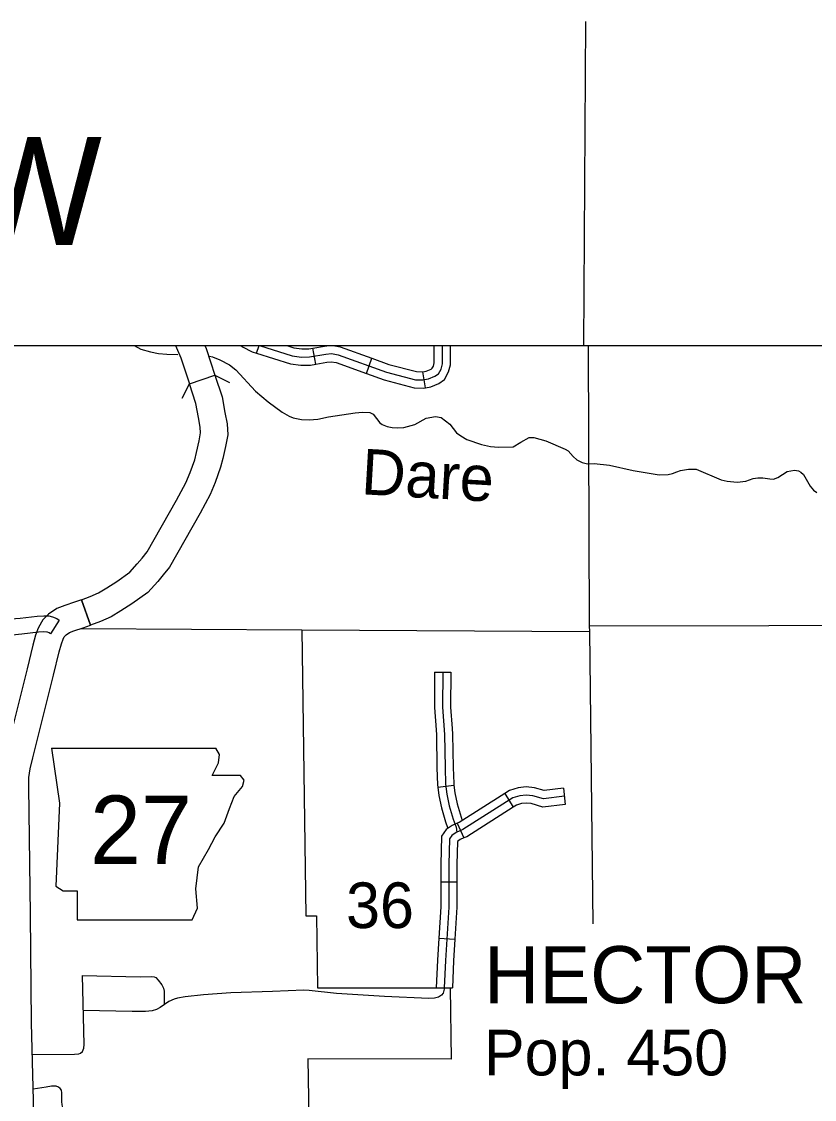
# Model space of a CAD drawing. Extents: x 1373862 to 1376999, y 1168398 to 1170455.
# Drawn here: x 1374821 to 1374967.8, y 1169439.9 to 1169639.4 of the extents above; entities that cross this region are included whole.
import ezdxf

# ---------------------------------------------------------------- set-up
doc = ezdxf.new("R2010")
doc.units = 0
for name, color, linetype in [('Level 10', 7, 'Continuous'), ('Level 21', 7, 'Continuous'), ('Level 24', 7, 'Continuous'), ('Level 31', 7, 'Continuous'), ('Level 32', 7, 'Continuous'), ('Level 33', 7, 'Continuous'), ('Level 34', 7, 'Continuous'), ('Level 35', 7, 'Continuous'), ('Level 37', 7, 'Continuous'), ('Level 4', 7, 'Continuous'), ('Level 45', 7, 'Continuous'), ('Level 5', 7, 'Continuous'), ('Level 6', 7, 'Continuous'), ('R_Dimension', 7, 'Continuous'), ('R_Draft', 7, 'Continuous')]:
    doc.layers.add(name, color=color, linetype=linetype)

msp = doc.modelspace()

# ---------------------------------------------------------------- linework, layer by layer
at = {"layer": 'Level 10'}
for p, q in [((1374852.08, 1169572.38), (1374856.82, 1169573.97)), ((1374833.79, 1169527.69), (1374832.11, 1169532.4)), ((1374832.11, 1169532.4), (1374833.79, 1169527.69)), ((1374833.79, 1169527.69), (1374832.11, 1169532.4))]:
    msp.add_line(p, q, dxfattribs=at)
for points in [[(1374849.53, 1169579.43), (1374849.72, 1169579.03), (1374850.48, 1169577.15), (1374852.08, 1169572.38)], [(1374854.95, 1169579.43), (1374855.17, 1169578.88), (1374856.82, 1169573.97)], [(1374856.82, 1169573.97), (1374858.16, 1169569.98), (1374858.66, 1169567.06), (1374859.07, 1169564.98), (1374859.18, 1169562.94), (1374858.78, 1169560.78), (1374858.25, 1169558.52), (1374857.87, 1169556.91), (1374856.87, 1169554.11), (1374855.93, 1169551.89), (1374854.07, 1169548.42), (1374848.39, 1169538.45), (1374847.22, 1169536.98), (1374846.23, 1169535.76), (1374844.38, 1169533.73), (1374841.44, 1169531.61), (1374839.41, 1169530.35), (1374837.58, 1169529.26), (1374835.63, 1169528.35), (1374833.79, 1169527.69)], [(1374832.11, 1169532.4), (1374833.73, 1169532.98), (1374835.24, 1169533.68), (1374836.81, 1169534.62), (1374838.66, 1169535.77), (1374841.04, 1169537.48), (1374842.44, 1169539.02), (1374843.32, 1169540.11), (1374844.24, 1169541.26), (1374849.69, 1169550.84), (1374851.41, 1169554.05), (1374852.21, 1169555.93), (1374853.07, 1169558.32), (1374853.38, 1169559.65), (1374853.88, 1169561.8), (1374854.15, 1169563.27), (1374854.1, 1169564.37), (1374853.75, 1169566.16), (1374853.3, 1169568.75), (1374852.08, 1169572.38)], [(1374832.11, 1169532.4), (1374830.81, 1169531.92), (1374829.04, 1169531.36), (1374827.55, 1169530.79), (1374826.02, 1169529.74), (1374824.96, 1169528.66), (1374824.68, 1169528.26), (1374824.12, 1169527.12), (1374823.62, 1169525.83), (1374823.12, 1169524.01), (1374822.08, 1169519.63), (1374818.21, 1169504.28), (1374817.73, 1169502.04), (1374817.38, 1169499.94), (1374817.35, 1169497.74), (1374817.69, 1169474.07), (1374817.87, 1169454.03), (1374818.37, 1169434.73), (1374818.71, 1169423.46)], [(1374823.71, 1169423.61), (1374823.36, 1169434.87), (1374822.87, 1169454.11), (1374822.69, 1169474.13), (1374822.35, 1169497.74), (1374822.37, 1169499.49), (1374822.64, 1169501.1), (1374823.08, 1169503.14), (1374826.94, 1169518.45), (1374827.96, 1169522.77), (1374828.38, 1169524.26), (1374828.7, 1169525.12), (1374828.92, 1169525.55), (1374829.25, 1169525.9), (1374829.88, 1169526.33), (1374830.68, 1169526.63), (1374832.43, 1169527.19), (1374833.79, 1169527.69)]]:
    msp.add_lwpolyline(points, dxfattribs=at)
at = {"layer": 'Level 21'}
for p, q in [((1374826.54, 1169504.92), (1374828.07, 1169494.77)), ((1374857.67, 1169503.74), (1374856.97, 1169504.91)), ((1374857.5, 1169502.22), (1374857.67, 1169503.74)), ((1374856.32, 1169499.85), (1374857.5, 1169502.22)), ((1374861.56, 1169499.85), (1374856.32, 1169499.85)), ((1374862.24, 1169499), (1374861.56, 1169499.85)), ((1374860.38, 1169495.96), (1374861.9, 1169497.82)), ((1374861.9, 1169497.82), (1374862.24, 1169499)), ((1374859.53, 1169493.76), (1374860.38, 1169495.96)), ((1374828.07, 1169494.77), (1374827.39, 1169479.38)), ((1374858.52, 1169491.05), (1374859.53, 1169493.76)), ((1374856.83, 1169488.51), (1374858.52, 1169491.05)), ((1374855.64, 1169486.14), (1374856.83, 1169488.51)), ((1374853.78, 1169482.93), (1374855.64, 1169486.14)), ((1374853.27, 1169478.87), (1374853.78, 1169482.93)), ((1374827.39, 1169479.38), (1374828.74, 1169478.53)), ((1374828.74, 1169478.53), (1374831.28, 1169478.53)), ((1374831.28, 1169478.53), (1374831.28, 1169473.12)), ((1374853.61, 1169475.32), (1374853.27, 1169478.87)), ((1374852.6, 1169473.12), (1374853.61, 1169475.32)), ((1374831.28, 1169473.12), (1374852.6, 1169473.12))]:
    msp.add_line(p, q, dxfattribs=at)
msp.add_lwpolyline([(1374826.54, 1169504.92), (1374856.97, 1169504.91)], dxfattribs=at)
at = {"layer": 'Level 31'}
msp.add_line((1374828, 1169528.61), (1374826.36, 1169526.1), dxfattribs=at)
for points in [[(1374816.7, 1169528.68), (1374816.81, 1169528.68), (1374819.03, 1169528.84), (1374820.74, 1169528.99), (1374823.89, 1169529.37), (1374825.13, 1169529.44), (1374826.05, 1169529.4), (1374826.74, 1169529.25), (1374827.53, 1169528.92), (1374828, 1169528.61)], [(1374826.36, 1169526.1), (1374826.12, 1169526.26), (1374825.85, 1169526.37), (1374825.67, 1169526.41), (1374825.15, 1169526.43), (1374824.15, 1169526.38), (1374821.05, 1169526), (1374819.27, 1169525.85), (1374816.99, 1169525.69), (1374816.86, 1169525.68)]]:
    msp.add_lwpolyline(points, dxfattribs=at)
at = {"layer": 'Level 32'}
for p, q in [((1374864.53, 1169578.02), (1374864.97, 1169579.43)), ((1374875.48, 1169576.02), (1374874.96, 1169578.98)), ((1374884.86, 1169574.28), (1374885.87, 1169577.1)), ((1374895.78, 1169571.65), (1374895.3, 1169574.61)), ((1374921.3, 1169497.5), (1374921.66, 1169494.52)), ((1374910.44, 1169496.52), (1374912.04, 1169493.98)), ((1374901.67, 1169491.04), (1374902.89, 1169488.3)), ((1374898.61, 1169480.21), (1374901.61, 1169480.21)), ((1374898.25, 1169469.75), (1374901.24, 1169469.57))]:
    msp.add_line(p, q, dxfattribs=at)
for points in [[(1374861.58, 1169579.43), (1374861.89, 1169579.19), (1374863.68, 1169578.28), (1374864.53, 1169578.02)], [(1374865.05, 1169579.43), (1374871.09, 1169577.54), (1374872.82, 1169577.33), (1374874.34, 1169577.35), (1374877.31, 1169577.87), (1374878.38, 1169577.95), (1374879.6, 1169577.76), (1374888.56, 1169574.54), (1374893.92, 1169573.13), (1374895.3, 1169573.09), (1374896.32, 1169573.26), (1374897.53, 1169573.78), (1374898.17, 1169574.19), (1374898.66, 1169575.11), (1374898.91, 1169576.07), (1374898.91, 1169579.43)], [(1374870.09, 1169579.43), (1374871.41, 1169579.02), (1374872.9, 1169578.83), (1374874.2, 1169578.84), (1374874.96, 1169578.98)], [(1374874.96, 1169578.98), (1374877.12, 1169579.36), (1374877.97, 1169579.43)], [(1374878.67, 1169579.43), (1374879.98, 1169579.22), (1374885.87, 1169577.1)], [(1374895.3, 1169574.61), (1374895.89, 1169574.71), (1374896.83, 1169575.11), (1374897.03, 1169575.25), (1374897.26, 1169575.66), (1374897.41, 1169576.26), (1374897.41, 1169579.43)], [(1374895.78, 1169571.65), (1374896.74, 1169571.81), (1374898.24, 1169572.45), (1374899.31, 1169573.14), (1374900.07, 1169574.56), (1374900.41, 1169575.87), (1374900.41, 1169579.43)], [(1374864.53, 1169578.02), (1374870.77, 1169576.07), (1374872.73, 1169575.83), (1374874.48, 1169575.85), (1374875.48, 1169576.02)], [(1374885.87, 1169577.1), (1374889.01, 1169575.97), (1374894.13, 1169574.62), (1374895.2, 1169574.6), (1374895.3, 1169574.61)], [(1374875.48, 1169576.02), (1374877.5, 1169576.38), (1374878.32, 1169576.44), (1374879.23, 1169576.3), (1374884.86, 1169574.28)], [(1374884.86, 1169574.28), (1374888.12, 1169573.1), (1374893.71, 1169571.63), (1374895.4, 1169571.59), (1374895.78, 1169571.65)], [(1374921.3, 1169497.5), (1374917.76, 1169497.07), (1374915.93, 1169497.61), (1374914.42, 1169497.75), (1374912.95, 1169497.6), (1374911.33, 1169497.09), (1374910.44, 1169496.52)], [(1374921.48, 1169496.01), (1374917.63, 1169495.54), (1374915.65, 1169496.13), (1374914.42, 1169496.24), (1374913.26, 1169496.13), (1374911.97, 1169495.72), (1374902.72, 1169489.86), (1374901.46, 1169489.3), (1374900.66, 1169488.75), (1374900.22, 1169488.15), (1374900.11, 1169483.39), (1374900.1, 1169475.52), (1374899.49, 1169465.63), (1374899.25, 1169460.57)], [(1374910.44, 1169496.52), (1374902.01, 1169491.19), (1374901.67, 1169491.04)], [(1374912.04, 1169493.98), (1374903.42, 1169488.53), (1374902.89, 1169488.3)], [(1374921.66, 1169494.52), (1374917.5, 1169494.02), (1374915.36, 1169494.65), (1374914.43, 1169494.73), (1374913.56, 1169494.65), (1374912.61, 1169494.35), (1374912.04, 1169493.98)], [(1374901.67, 1169491.04), (1374900.73, 1169490.62), (1374899.6, 1169489.84), (1374898.73, 1169488.66), (1374898.61, 1169483.41), (1374898.61, 1169480.21)], [(1374902.89, 1169488.3), (1374902.2, 1169487.99), (1374901.72, 1169487.66), (1374901.71, 1169487.65), (1374901.61, 1169483.37), (1374901.61, 1169480.21)], [(1374898.61, 1169480.21), (1374898.6, 1169475.57), (1374898.25, 1169469.75)], [(1374901.61, 1169480.21), (1374901.6, 1169475.47), (1374901.24, 1169469.57)], [(1374898.25, 1169469.75), (1374898, 1169465.71), (1374897.75, 1169460.57), (1374900.75, 1169460.57)], [(1374901.24, 1169469.57), (1374900.99, 1169465.54), (1374900.75, 1169460.57)]]:
    msp.add_lwpolyline(points, dxfattribs=at)
at = {"layer": 'Level 33'}
for points in [[(1374823.02, 1169448.19), (1374830.82, 1169448.25), (1374831.59, 1169448.31), (1374831.91, 1169448.44), (1374832.27, 1169448.8), (1374832.54, 1169449.37), (1374832.59, 1169450.05), (1374832.29, 1169462.84)], [(1374874.24, 1169460.09), (1374873.26, 1169460.12), (1374867.49, 1169459.9), (1374859.74, 1169459.63), (1374854.68, 1169459.27), (1374851.31, 1169458.92), (1374849.86, 1169458.65), (1374849.24, 1169458.45), (1374848.29, 1169458.02), (1374846.65, 1169456.9), (1374845.97, 1169456.52), (1374845.18, 1169456.28), (1374843.93, 1169456.17), (1374841.51, 1169456.17), (1374832.44, 1169456.39)], [(1374834.79, 1169433.95), (1374834.54, 1169437.35), (1374834.43, 1169437.73), (1374834.25, 1169437.95), (1374834.02, 1169438.04), (1374833.69, 1169438.09), (1374833.4, 1169438.06), (1374830.73, 1169437.54), (1374830.2, 1169437.5), (1374829.68, 1169437.56), (1374829.28, 1169437.68), (1374828.9, 1169438.01), (1374828.67, 1169438.43), (1374828.53, 1169438.89), (1374828.47, 1169439.54), (1374828.5, 1169441.1), (1374828.42, 1169441.6), (1374828.18, 1169441.93), (1374827.86, 1169442.2), (1374827.4, 1169442.35), (1374827.03, 1169442.38), (1374826.55, 1169442.37), (1374825.56, 1169442.2), (1374823.19, 1169441.77)]]:
    msp.add_lwpolyline(points, dxfattribs=at)
at = {"layer": 'Level 34'}
for points in [[(1374832.29, 1169462.84), (1374842.96, 1169462.62), (1374845.1, 1169462.67), (1374845.54, 1169462.62), (1374845.84, 1169462.46), (1374846.33, 1169461.97), (1374846.98, 1169461.1), (1374847.28, 1169460.47), (1374847.42, 1169459.95), (1374847.44, 1169457.44)], [(1374899.25, 1169460.57), (1374899.24, 1169460.3), (1374899.04, 1169459.55), (1374898.76, 1169459.23), (1374898.72, 1169459.2), (1374898.21, 1169458.85), (1374897.44, 1169458.65), (1374896.4, 1169458.58), (1374888.21, 1169458.94), (1374879.33, 1169459.53), (1374874.24, 1169460.09)]]:
    msp.add_lwpolyline(points, dxfattribs=at)
at = {"layer": 'Level 35'}
for points in [[(1374841.83, 1169579.43), (1374843.08, 1169578.81), (1374844.87, 1169578.27), (1374846.34, 1169577.95), (1374847.92, 1169577.83), (1374849.94, 1169577.81)], [(1374855.81, 1169577.46), (1374856.38, 1169577.36), (1374857.73, 1169576.83), (1374859.51, 1169575.9), (1374860.68, 1169574.97), (1374864.32, 1169571.01), (1374866.69, 1169569.05), (1374869.26, 1169567.15), (1374870.52, 1169566.4), (1374871.31, 1169566.1), (1374872.86, 1169565.74), (1374874.24, 1169565.68), (1374875.88, 1169565.82), (1374877.85, 1169566.28), (1374882.75, 1169566.97), (1374884.15, 1169567.09), (1374885.51, 1169567.04), (1374886.1, 1169566.72), (1374887.32, 1169565.17), (1374887.79, 1169564.84), (1374888.7, 1169564.48), (1374889.6, 1169564.27), (1374890.6, 1169564.19), (1374891.76, 1169564.28), (1374893.81, 1169564.86), (1374895.9, 1169565.98), (1374897.63, 1169566.29), (1374898.67, 1169566.13), (1374899.49, 1169565.53), (1374900.31, 1169564.87), (1374901.53, 1169563.32), (1374902.3, 1169562.74), (1374903.42, 1169562.09), (1374906.17, 1169561.14), (1374907.84, 1169560.76), (1374909.32, 1169560.62), (1374912.04, 1169560.69), (1374913.45, 1169561.59), (1374914.99, 1169562.4), (1374915.83, 1169562.44), (1374918.07, 1169561.84), (1374921.63, 1169560.27), (1374922.2, 1169559.96), (1374923.1, 1169558.94), (1374923.82, 1169558.32), (1374924.75, 1169557.78), (1374925.76, 1169557.57), (1374927, 1169557.64), (1374929.83, 1169557.28), (1374934.21, 1169556.35), (1374939.01, 1169555.54), (1374940.71, 1169555.6), (1374941.47, 1169555.76), (1374942.28, 1169556.07)], [(1374942.28, 1169556.07), (1374943, 1169556.31), (1374944.45, 1169556.59), (1374945.91, 1169556.56), (1374950.52, 1169554.62), (1374951.61, 1169554.33), (1374953.47, 1169554.18), (1374955.05, 1169554.32), (1374956.46, 1169554.82), (1374957.27, 1169554.96), (1374958.19, 1169554.99), (1374959.5, 1169554.76), (1374960.18, 1169554.74), (1374961.01, 1169555.04), (1374962.7, 1169556.15), (1374964.1, 1169556.37), (1374964.8, 1169556.25), (1374965.23, 1169556.02), (1374965.72, 1169555.57), (1374967.01, 1169553.42), (1374967.61, 1169552.71), (1374968.22, 1169552.23)]]:
    msp.add_lwpolyline(points, dxfattribs=at)
at = {"layer": 'Level 37'}
for points in [[(1374856.82, 1169573.97), (1374859.51, 1169572.64)], [(1374850.75, 1169569.69), (1374852.08, 1169572.38)]]:
    msp.add_lwpolyline(points, dxfattribs=at)
at = {"layer": 'Level 4'}
msp.add_lwpolyline([(1374925.92, 1169579.43), (1374926.1, 1169527.55), (1374926.11, 1169526.53), (1374926.76, 1169472.39)], dxfattribs=at)
at = {"layer": 'Level 45'}
for p, q in [((1374897.48, 1169519), (1374900.48, 1169518.98)), ((1374898.06, 1169497.72), (1374901.04, 1169498.06))]:
    msp.add_line(p, q, dxfattribs=at)
for points in [[(1374897.48, 1169519), (1374897.43, 1169512.44), (1374897.73, 1169508.33)], [(1374898.98, 1169518.99), (1374898.93, 1169512.49), (1374899.3, 1169507.46), (1374899.4, 1169501.33), (1374899.51, 1169498.26), (1374899.72, 1169496.41), (1374900.19, 1169494.24), (1374900.93, 1169491.76), (1374901.46, 1169490.27), (1374901.61, 1169489.37)], [(1374900.48, 1169518.98), (1374900.43, 1169512.53), (1374900.72, 1169508.55)], [(1374897.73, 1169508.33), (1374897.8, 1169507.39), (1374897.9, 1169501.29), (1374898.01, 1169498.15), (1374898.06, 1169497.72)], [(1374900.72, 1169508.55), (1374900.79, 1169507.53), (1374900.9, 1169501.37), (1374901, 1169498.37), (1374901.04, 1169498.06)], [(1374898.06, 1169497.72), (1374898.24, 1169496.16), (1374898.74, 1169493.87), (1374899.51, 1169491.29), (1374899.88, 1169490.23)], [(1374901.04, 1169498.06), (1374901.2, 1169496.66), (1374901.65, 1169494.62), (1374902.56, 1169491.54)]]:
    msp.add_lwpolyline(points, dxfattribs=at)
at = {"layer": 'Level 5'}
for points in [[(1374926.1, 1169527.55), (1375025.83, 1169527.76)], [(1374872.9, 1169526.83), (1374926.11, 1169526.53)]]:
    msp.add_lwpolyline(points, dxfattribs=at)
at = {"layer": 'Level 6'}
for points in [[(1374832.06, 1169527.07), (1374872.9, 1169526.83), (1374873.65, 1169473.87), (1374875.63, 1169473.86), (1374875.82, 1169460.58), (1374900.36, 1169460.57), (1374900.55, 1169447.37), (1374874.03, 1169447.39)], [(1374874.03, 1169447.39), (1374876.2, 1169316.39), (1374825.49, 1169317.04)]]:
    msp.add_lwpolyline(points, dxfattribs=at)
at = {"layer": 'R_Dimension'}
msp.add_line((1374925.41, 1169639.43), (1374925, 1169579.43), dxfattribs=at)
at = {"layer": 'R_Draft'}
msp.add_lwpolyline([(1374675.34, 1169579.43), (1376182.76, 1169579.43), (1376182.76, 1168562.99), (1374675.34, 1168562.99)], close=True, dxfattribs=at)

# ---------------------------------------------------------------- texts
at = {"layer": 'Level 21'}
msp.add_text('27', height=12.672, dxfattribs=at).set_placement((1374833.69, 1169483.48))
at = {"layer": 'Level 24'}
for s, height, p in [('HECTOR', 10.56, (1374906.65, 1169457.71)), ('Pop. 450', 8.448, (1374906.59, 1169444.35))]:
    msp.add_text(s, height=height, dxfattribs=at).set_placement(p)
at = {"layer": 'Level 35'}
msp.add_text('Dare', height=8.448, rotation=356.6996, dxfattribs=at).set_placement((1374883.75, 1169551.94))
at = {"layer": 'Level 5'}
msp.add_text('36', height=8.448, dxfattribs=at).set_placement((1374881.08, 1169471.62))
at = {"layer": 'Level 6'}
for s, height, p in [('HECTOR', 10.56, (1374906.65, 1169457.71)), ('Pop. 450', 8.448, (1374906.59, 1169444.35))]:
    msp.add_text(s, height=height, dxfattribs=at).set_placement(p)
at = {"layer": 'R_Draft'}
msp.add_text('R 19 W', height=20, dxfattribs=at).set_placement((1374746.73, 1169598.07))

doc.saveas('drawing.dxf')
